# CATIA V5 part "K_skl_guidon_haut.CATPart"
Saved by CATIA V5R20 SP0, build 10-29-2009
Part number: skl_guidon_haut
Publications: "Axe_guidon_haut_guidon", "Plan_guidon_haut_poignet"
Bounding box of the stored display mesh (mm): x 0 to 0, y 0 to 0, z 350 to 670
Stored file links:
  G:\Khaled_CFAO_2011\SIL\SIL_GR2\ahabrial\ahabrial\Khaled\CAD_ThinkMOTION\K_skl_guidon_haut.CATPart
  G:\Données\Ecole\IFMA\2A\Thinkmotion2\Etape18\trotinette.CATProduct
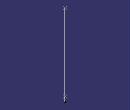
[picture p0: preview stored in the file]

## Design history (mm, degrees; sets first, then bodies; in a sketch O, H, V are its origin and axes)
Set1
  Point1: linked copy from another document
  Point2: linked copy from another document
Body1 (main body)
  Line1 "Droite_guidon_haut": type PtPt, FirstPoint Point1, SecondPoint Point2
  Line2 "Axe_guidon_haut_guidon": type PtDir, RefPoint Point2, Direction Line1, Start 0, End 20
  Plane1 "Plan_guidon_haut_poignet": type Normal, Curve Line1, RefPoint Point1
